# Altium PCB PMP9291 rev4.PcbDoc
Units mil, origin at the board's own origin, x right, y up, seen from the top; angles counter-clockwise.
Board outline 2000 x 2700 mil, 4 copper layers (Top Layer, MidLayer1, MidLayer2, Bottom Layer), stack 90 mil thick; 61 components, 21 nets, 125 pads, 4 vias.
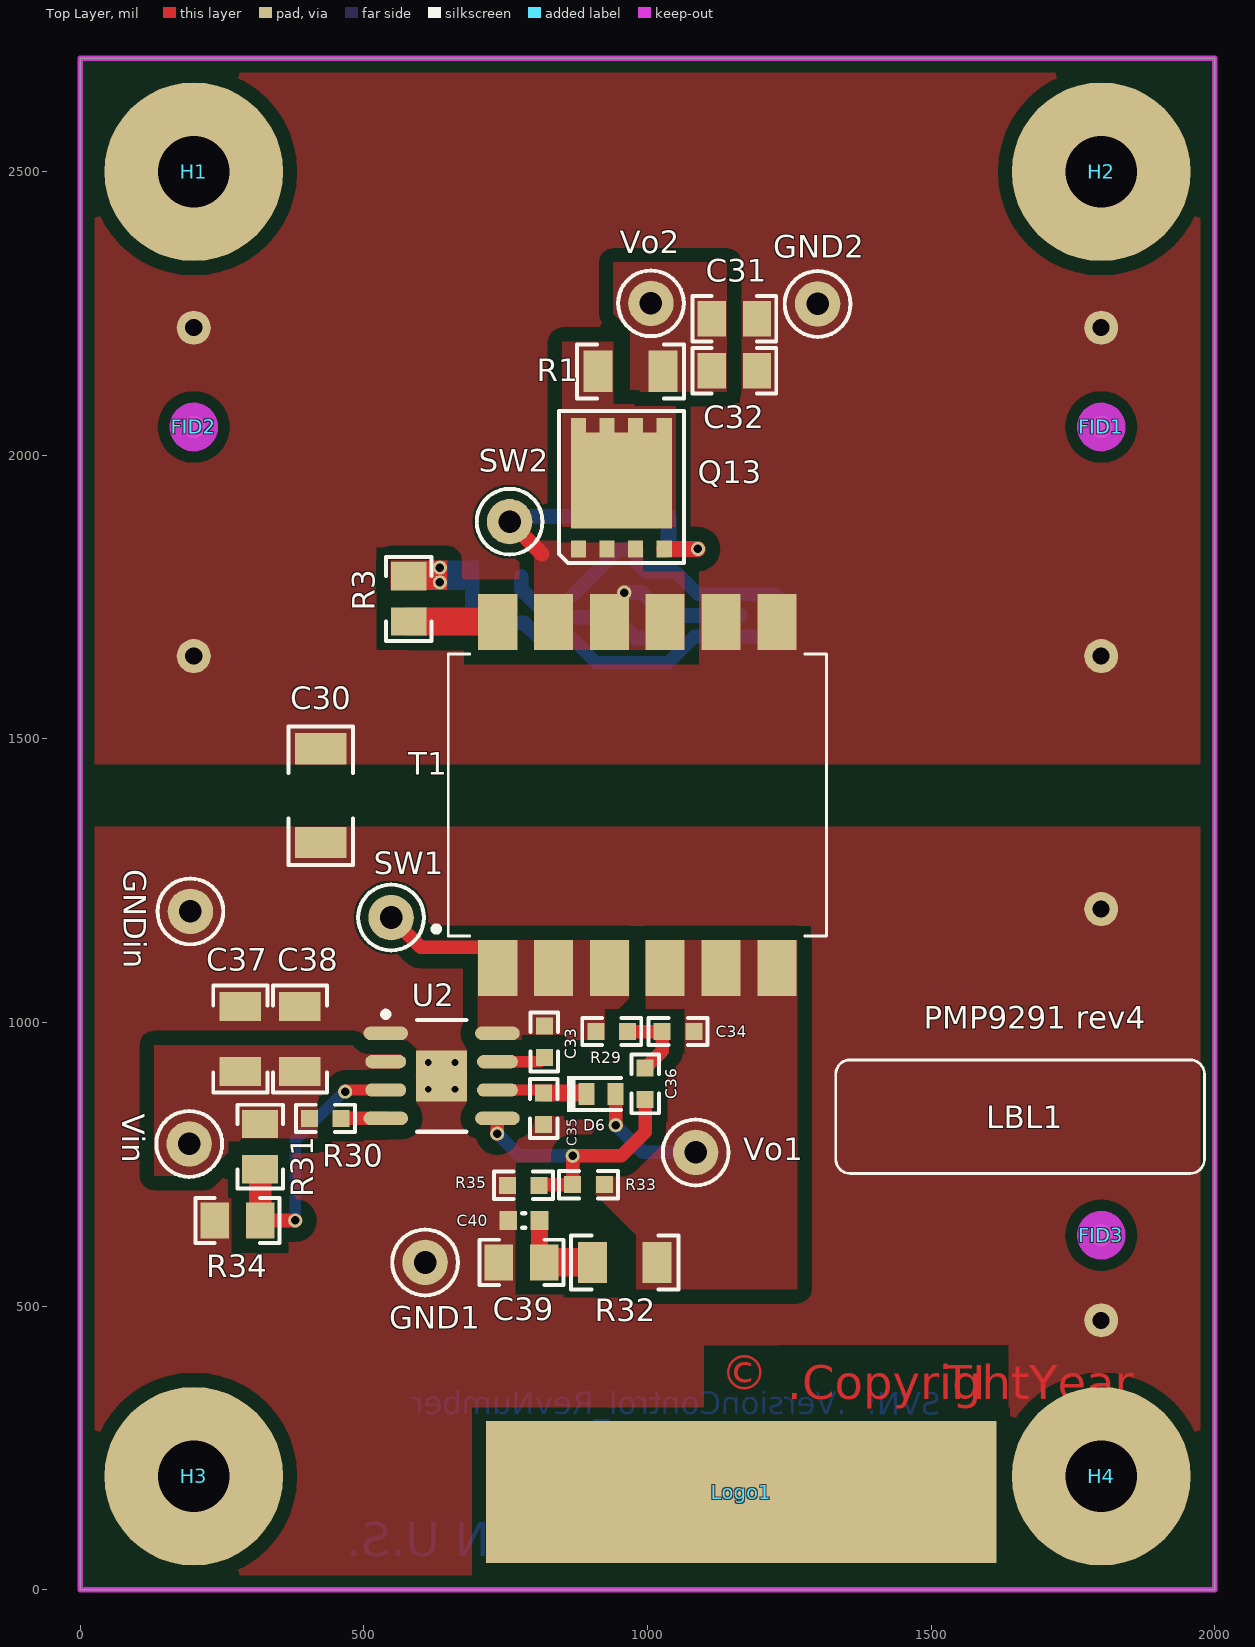
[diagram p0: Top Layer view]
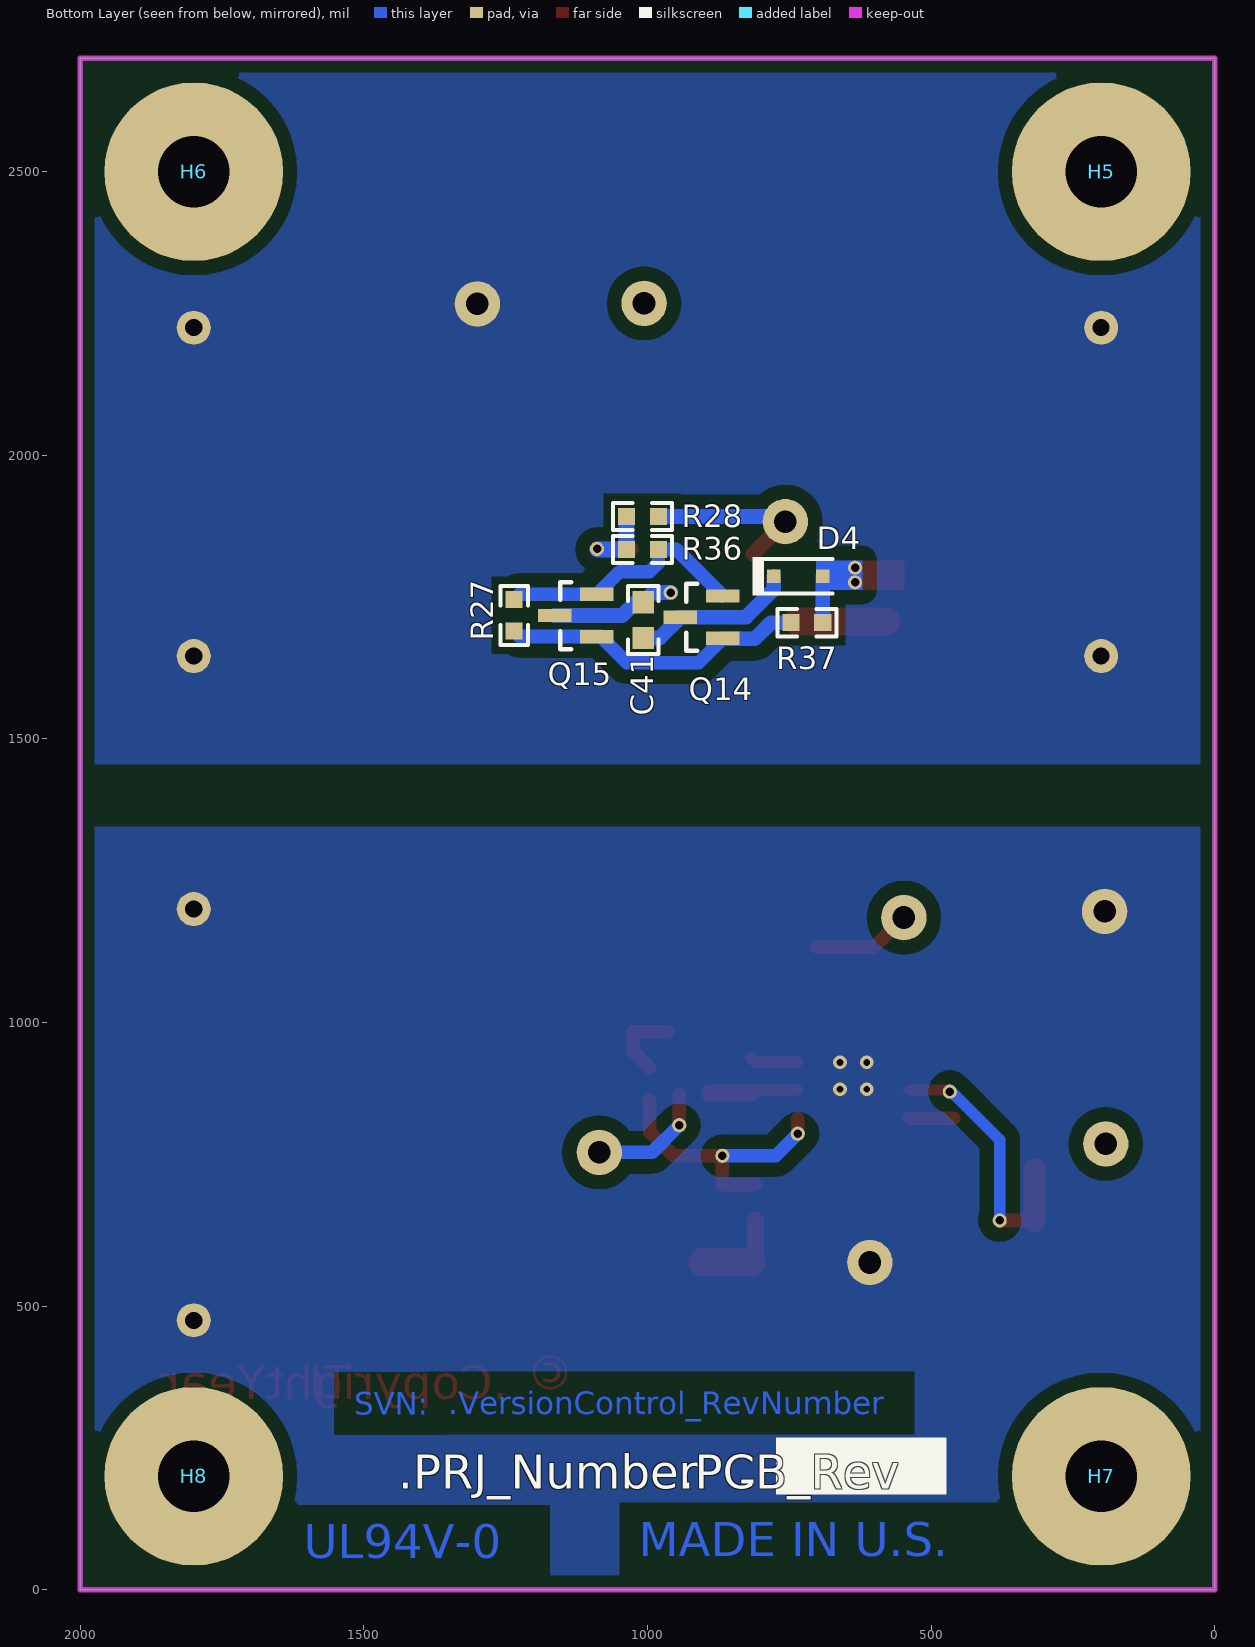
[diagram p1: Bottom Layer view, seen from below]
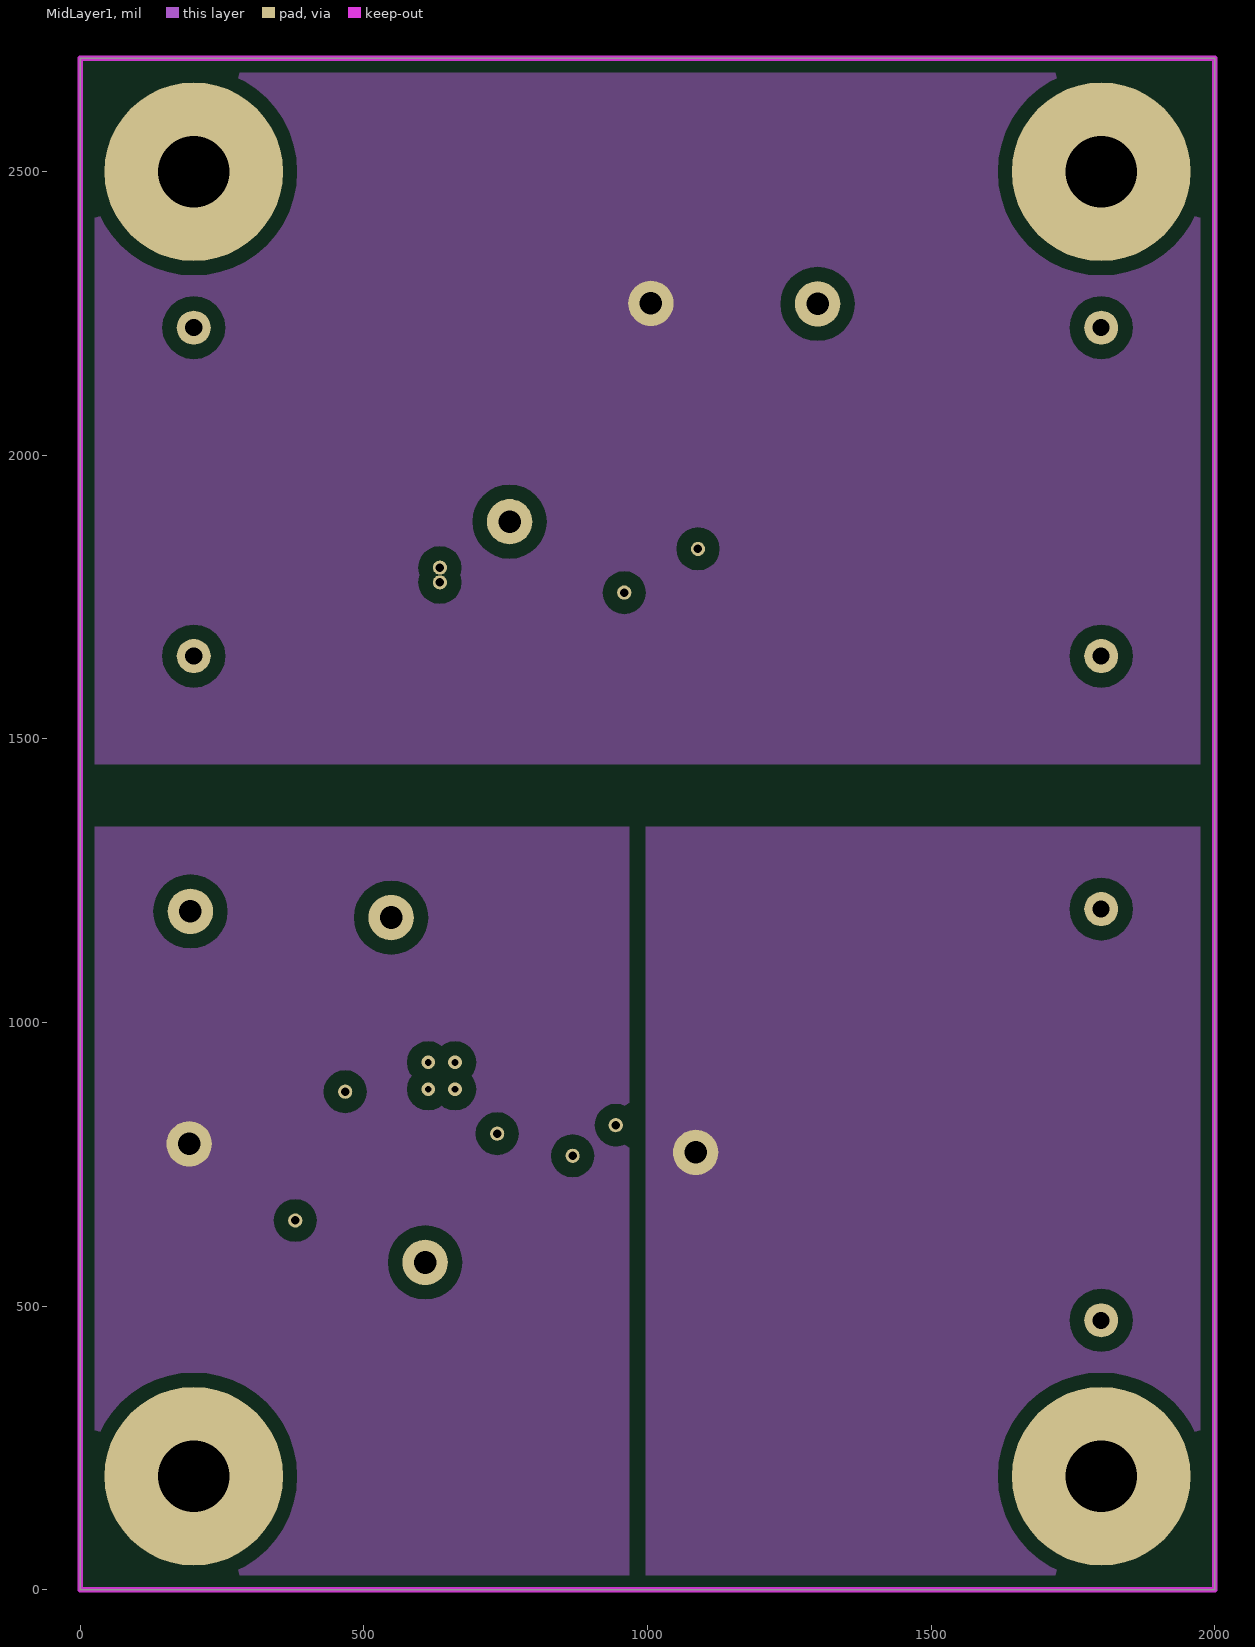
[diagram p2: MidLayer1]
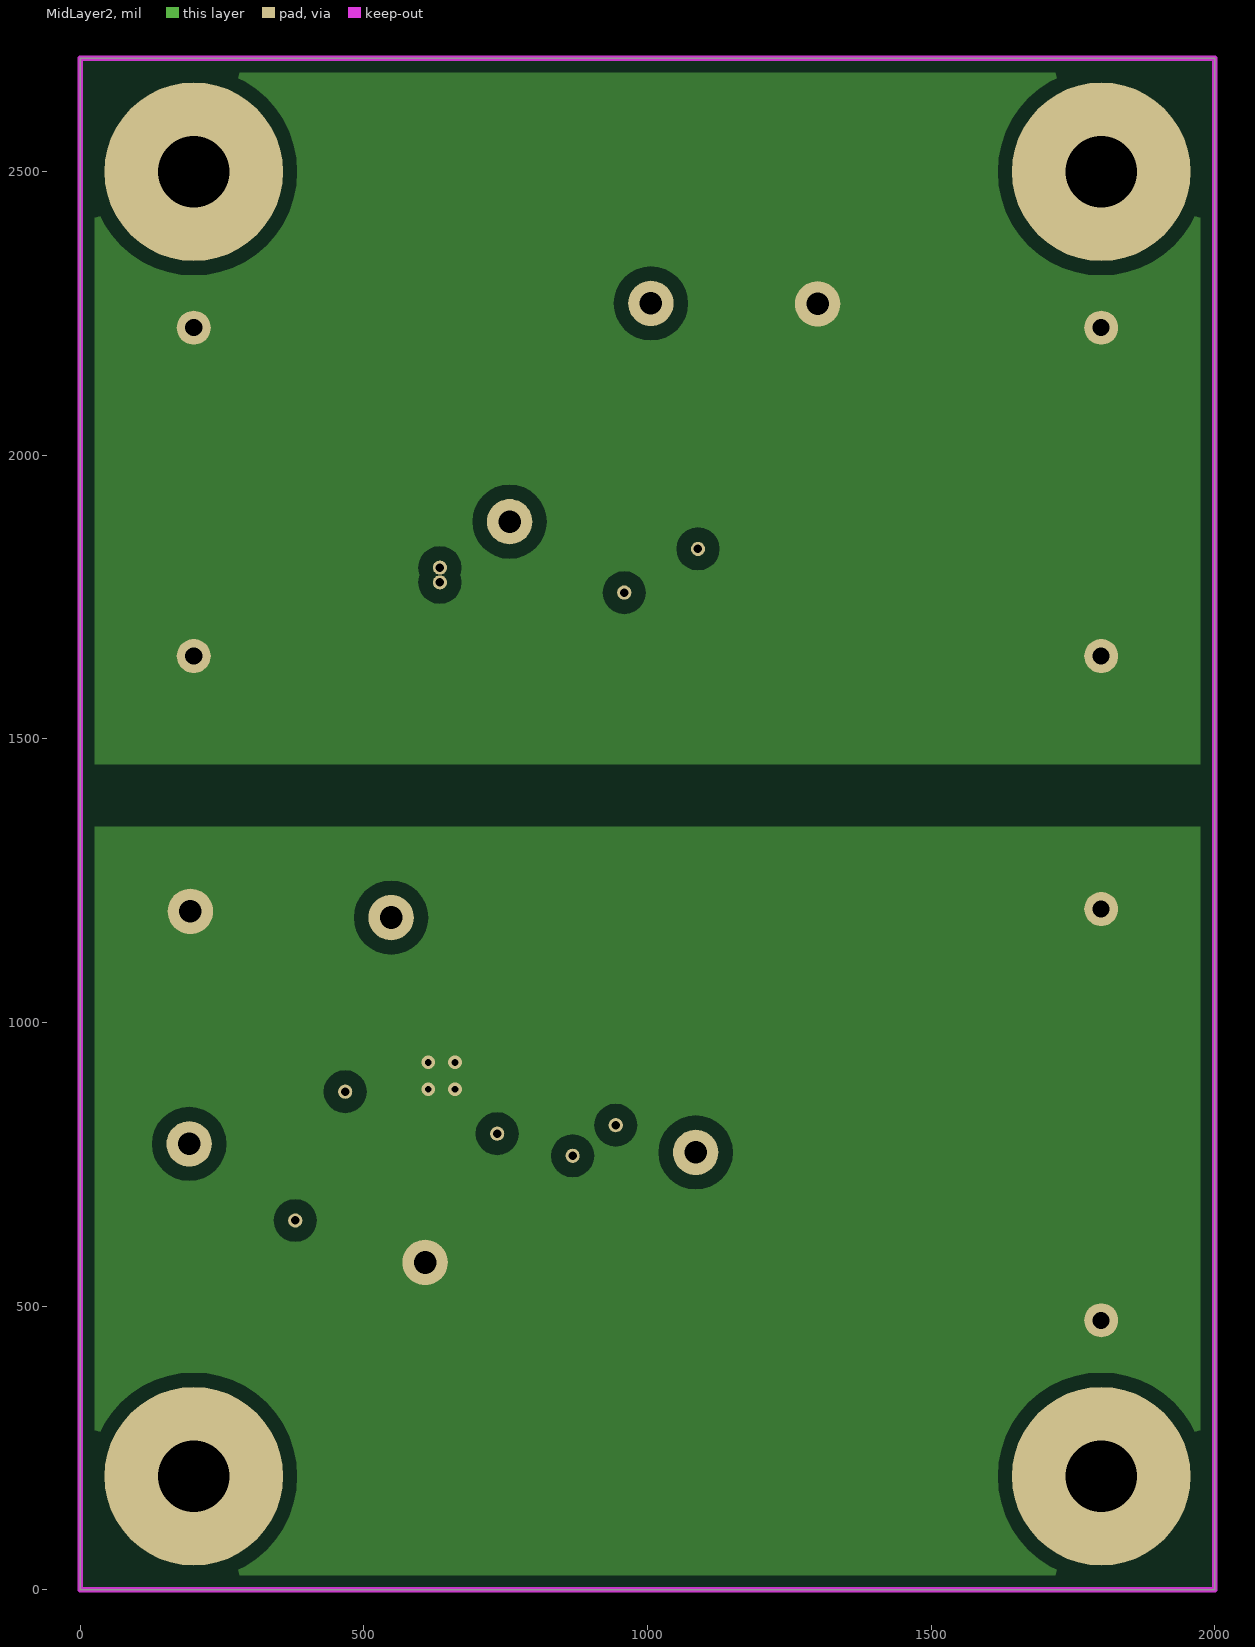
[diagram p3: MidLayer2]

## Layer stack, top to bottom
Top Solder: solder mask 0.4, Solder Resist, Dk 3.5
Top Layer: signal copper 1.4
Dielectric1: core 59.2, FR-4, Dk 4.8
MidLayer1: signal copper 1.4
Dielectric2: prepreg 12.6, FR-4, Dk 4.8
MidLayer2: signal copper 1.4
Dielectric3: core 12.6, FR-4, Dk 4.8
Bottom Layer: signal copper 1.4
Bottom Solder: solder mask 0.4, Solder Resist, Dk 3.5

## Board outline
0,0 2000,0 2000,2700 0,2700

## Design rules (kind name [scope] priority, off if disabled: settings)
AcuteAngle [All] p1: minimum=4.50000000000000E+0001 checktracksonly=FALSE
AssemblyTestPointUsage [All] p1: valid=2
Clearance Clearance_BoardEdge_MountingHoles [OnCopper and InComponentClass('Mounting Holes') vs IsKeepOut] p1: gap=30
Clearance Clearance_BoardEdge_Poly [OnCopper and InPoly vs IsKeepOut] p2: gap=20
Clearance Clearance_BoardEdge [OnCopper and Not InComponentClass('Logo') and not InComponentClass('FiducialMark') and not InRegion(1000,500,4000,800) and Not IsKeepout vs IsKeepOut] p3: gap=20
Clearance Clearance_Poly [InPolygon] p4: gap=25
Clearance [All] p5: gap=12
ComponentClearance ComponentClearance_Logo [InComponentClass('Logo')] p1: gap=20 collisioncheckmode=3 verticalgap=10 showdistances=FALSE
ComponentClearance ComponentClearance_ScrewToNut [(HasFootprint('NY PMS 440 0025 PH')) vs (HasFootprint('Keystone_1902C'))] p2: gap=5 collisioncheckmode=3 verticalgap=10 showdistances=FALSE
ComponentClearance ComponentClearance_MountingHoles [InComponentClass('Mounting Holes')] p3: gap=250 collisioncheckmode=3 verticalgap=100000 showdistances=FALSE
ComponentClearance ComponentClearance_SmallPassives [HasFootprint('0201*') or HasFootprint('0402*') or HasFootprint('0508') or HasFootprint('0603*') or HasFootprint('0612') or HasFootprint('0805*') or HasFootprint('0815*') or HasFootprint('0830*') or HasFootprint('1206*') or HasFootprint('1210*') or HasFootprint('1808*') or HasFootprint('1812*') or HasFootprint('1825*') or HasFootprint('2010*') or HasFootprint('2220*') or HasFootprint('2225*') or HasFootprint('2512*') or HasFootprint('2728*') or HasFootprint('3518*') vs HasFootprint('0201*') or HasFootprint('0402*') or HasFootprint('0508') or HasFootprint('0603*') or HasFootprint('0612') or HasFootprint('0805*') or HasFootprint('0815*') or HasFootprint('0830*') or HasFootprint('1206*') or HasFootprint('1210*') or HasFootprint('1808*') or HasFootprint('1812*') or HasFootprint('1825*') or HasFootprint('2010*') or HasFootprint('2220*') or HasFootprint('2225*') or HasFootprint('2512*') or HasFootprint('2728*') or HasFootprint('3518*')] p4: gap=20 collisioncheckmode=3 verticalgap=10 showdistances=FALSE
ComponentClearance ComponentClearance_THtoSMT [IsThruComponent vs IsSMTComponent] p5: gap=10 collisioncheckmode=3 verticalgap=30 showdistances=FALSE
ComponentClearance ComponentClearance_THtoTH [IsThruComponent vs IsThruComponent] p6: gap=10 collisioncheckmode=3 verticalgap=30 showdistances=FALSE
ComponentClearance [All] p7: gap=10 collisioncheckmode=3 verticalgap=10 showdistances=FALSE
DiffPairsRouting [All] p1: maxlimit=100 minlimit=10 mostfreqgap=10 toplayer_minwidth=15 toplayer_maxwidth=15 toplayer_prefwidth=15 midlayer1_minwidth=15 midlayer1_maxwidth=15 midlayer1_prefwidth=15 midlayer2_minwidth=15 midlayer2_maxwidth=15 midlayer2_prefwidth=15 bottomlayer_minwidth=15 bottomlayer_maxwidth=15 bottomlayer_prefwidth=15 maxuncoupledlength=1000
FabricationTestPointUsage TestPointUsage [All] p1: valid=2 allowmultiple=FALSE
FabricationTestpoint Testpoint [All] p1: side=3 testpointundercomponent=TRUE minsize=40 maxsize=100 preferedsize=60 minholesize=0 maxholesize=40 preferedholesize=32 testpointgrid=1 allowsidetop=TRUE allowsidebottom=TRUE usegrid=TRUE gridtolerance=0.01
FanoutControl Fanout_LCC [IsLCC] p1: bgadir=Out bgaviamode=Centered fanoutstyle=Auto fanoutdirection=Alternating viagrid=1 // Fanout_LCC (Default Rule)
FanoutControl Fanout_BGA [IsBGA] p2: bgadir=Out bgaviamode=Centered fanoutstyle=Auto fanoutdirection=Alternating viagrid=1 // Fanout_BGA (Default Rule)
FanoutControl Fanout_Default [All] p4: bgadir=Out bgaviamode=Centered fanoutstyle=Auto fanoutdirection=Alternating viagrid=1 // Fanout_Default (Default Rule)
FanoutControl Fanout_Small [(CompPinCount < 5)] p5: bgadir=Out bgaviamode=Centered fanoutstyle=Auto fanoutdirection=OutThenIn viagrid=1 // Fanout_Small (Default Rule)
HoleSize [All] p1: absolutevalues=TRUE maxlimit=251 minlimit=10 maxpercent=80.000 minpercent=20.000
MinimumAnnularRing MinimumAnnularRing_ThermalPadVias [IsVia and InAnyComponent] p1: minimumring=5.91
MinimumAnnularRing [All] p2: minimumring=5
MinimumSolderMaskSliver MinimumSolderMaskSliver_Logo [InComponentClass('Logo') vs InComponentClass('Logo')] p1: minsoldermaskwidth=0.7
MinimumSolderMaskSliver [All] p2: minsoldermaskwidth=3.94
PlaneClearance [All] p1: clearance=12
PlaneConnect [All] p1: planeconnectstyle=Direct reliefexpansion=10 reliefentries=4 reliefconductorwidth=10 reliefairgap=10
PolygonConnect [All] p1: connectstyle=Direct reliefconductorwidth=10 reliefentries=4 polygonreliefangle="90 Angle" airgapwidth=10
RoutingVias ThermalPadVias [IsVia and InAnyComponent] p1: holewidth=7.87 width=19.68 viastyle="Through Hole" minholewidth=7.87 minwidth=19.68 maxholewidth=12.99 maxwidth=23.62
RoutingVias [All] p2: holewidth=16 width=34 viastyle="Through Hole" minholewidth=7.87 minwidth=26 maxholewidth=40 maxwidth=65
SMDToCorner [All] p1: distance=30000
SilkToSilkClearance [All] p1: silktosilkclearance=5
SilkToSolderMaskClearance SilkscreenOverComponentPads [IsPad] p1: minsilkscreentomaskgap=5 clearancetoexposedcopper=TRUE
SolderMaskExpansion [All] p1: expansion=6
UnpouredPolygon [All] p1: allowunpoured=FALSE
Width [All] p1: maxlimit=100 minlimit=6 preferedwidth=10 checkconnectedcopper=TRUE
14 further rules are at their usual default settings.

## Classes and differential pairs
component class Label: LBL1
component class AssemblyNote: ZZ1 ZZ2 ZZ3 ZZ4
component class FiducialMark: FID1 FID2 FID3
component class "PMP9291 rev4 Hardware_ANSI-B": FID1 FID2 FID3 H1 H2 H3 H4 H5 H6 H7 H8 H9 H10 H11 H12 LBL1 Logo1 ZZ1 ZZ2 ZZ3 ZZ4
component class Logo: Logo1
component class "Mounting Holes": H1 H2 H3 H4
component class "PMP9291 Rev4 Schematic": C30 C31 C32 C33 C34 C35 C36 C37 C38 C39 C40 C41 D4 D6 GND1 GND2 GNDin Q13 Q14 Q15 R1 R3 R27 R28 R29 R30 R31 R32 R33 R34 R35 R36 R37 SW1 SW2 T1 U2 Vin Vo1 Vo2

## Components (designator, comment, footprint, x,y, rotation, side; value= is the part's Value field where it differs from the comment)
C30 "VJ1210Y102KXGAT5Z" 1808 424,1400 r90 top
C31 "2.2uF" 0805_HV 1153,2241 r0 top
C32 "2.2uF" 0805_HV 1153,2149 r0 top
C33 "GRM188R71C103KA01D" 0603_HV 818,966 r270 top
C34 "06035C104KAT2A" 0603_HV 1054,984 r180 top
C35 "C0603C105K4PACTU" 0603_HV 817,848 r270 top
C36 "06031C103JAT2A" 0603_HV 996,892 r270 top
C37 "GRM31CR61H225KA88L" 1206 282,971 r90 top
C38 "GRM31CR61H225KA88L" 1206 387,971 r90 top
C39 "C2012X7R1C225K" 0805_HV 778,577 r180 top
C40 "DNP" 0603L 782,651 r180 top
C41 "06035C104KAT2A" 0603 1007.44,1709.56 r90 bottom
D4 "BAS316,115" sod-323 734,1787 r180 bottom
D6 "CD0603-B0240" Diode_0603 918,874 r0 top
FID1 "Fiducial" Fiducial10-20 1800,2050 r0 top
FID2 "Fiducial" Fiducial10-20 200,2050 r0 top
FID3 "Fiducial" Fiducial10-20 1800,625 r0 top
GND1 "5001" Keystone5001 608,577 r0 top
GND2 "5001" Keystone5001 1300,2267 r90 top
GNDin "5001" Keystone5001 194,1196 r0 top
H1 "NY PMS 440 0025 PH" "NY PMS 440 0025 PH" 200,2500 r0 top locked
H2 "NY PMS 440 0025 PH" "NY PMS 440 0025 PH" 1800,2500 r0 top locked
H3 "NY PMS 440 0025 PH" "NY PMS 440 0025 PH" 200,200 r0 top locked
H4 "NY PMS 440 0025 PH" "NY PMS 440 0025 PH" 1800,200 r0 top locked
H5 "1902C" Keystone_1902C 200,2500 r180 bottom locked
H6 "1902C" Keystone_1902C 1800,2500 r180 bottom locked
H7 "1902C" Keystone_1902C 200,200 r180 bottom locked
H8 "1902C" Keystone_1902C 1800,200 r180 bottom locked
H9 "SJ-5303 (CLEAR)" Bumpon_SJ5003Transparent 7730,2620 r180 bottom
H10 "SJ-5303 (CLEAR)" Bumpon_SJ5003Transparent 8510,2720 r180 bottom
H11 "SJ-5303 (CLEAR)" Bumpon_SJ5003Transparent 7540,1640 r180 bottom
H12 "SJ-5303 (CLEAR)" Bumpon_SJ5003Transparent 8440,1640 r180 bottom
LBL1 "Size: 0.65\" x 0.20 \"" Label_650x200 1657,834 r0 top
Logo1 "Texas Instruments" TI_Stacked_SolderMask_Small 1165,172 r0 top
Q13 "CSD18537NQ5A" TRANS_NexFET_Q5A 954,1944 r90 top
Q14 "MMBT3904-7-F" SOT-23 904.44,1714.56 r0 bottom
Q15 "MMBT3906" SOT-23 1126.44,1717.56 r0 bottom
R1 "CRCW12060000Z0EA" 1206 970,2148 r0 top
R3 "CRCW08050000Z0EA" 0805_HV 579,1747 r90 top
R27 "CRCW060310R0JNEA" 0603_HV 1235,1718 r90 bottom
R28 "CRCW06032K00FKEA" 0603_HV 1009,1892 r180 bottom
R29 "CRCW060310K0FKEA" 0603_HV 937,984 r0 top
R30 "CRCW0603137KFKEA" 0603_HV 432,831 r0 top
R31 "CRCW0805127KFKEA" 0805_HV 317,781 r90 top
R32 "CRCW12060000Z0EA" 1206 960,577 r0 top
R33 "CRCW06036K04FKEA" 0603_HV 896,714 r0 top
R34 "DNP" 0805_HV 277,651 r0 top
R35 "CRCW06032K00FKEA" 0603_HV 781,713 r0 top
R36 "CRCW060310R0JNEA" 0603_HV 1009,1834 r180 bottom
R37 "CRCW06031K00FKEA" 0603_HV 719,1705 r0 bottom
SW1 "5000" Keystone5000 548,1185 r0 top
SW2 "5000" Keystone5000 757,1883 r0 top
T1 "VP2xxxx_VPH2xxxx" VP2_VPH2 982,1401 r90 top
U2 "LM5017MR" MRA08A_N 637,906 r0 top
Vin "5000" Keystone5000 192,786 r0 top
Vo1 "5000" Keystone5000 1085,771 r0 top
Vo2 "5000" Keystone5000 1006,2268 r270 top
ZZ1 "This Assembly Note is for PCB labels only" AssemblyNoteLabel 185,3938 r0 top
ZZ2 "These assemblies are ESD sensitive, ESD precautions shall be observed." AssemblyNote 185,3829.11 r0 top
ZZ3 "These assemblies must be clean and free from flux and all contaminants. Use of no clean flux is not acceptable." AssemblyNote 185,3740.56 r0 top
ZZ4 "These assemblies must comply with workmanship standards IPC-A-610 Class 2, unless otherwise specified." AssemblyNote 185,3652 r0 top

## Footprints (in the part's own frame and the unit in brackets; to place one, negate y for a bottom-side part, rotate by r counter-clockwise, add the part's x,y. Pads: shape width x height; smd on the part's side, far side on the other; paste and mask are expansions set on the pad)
0603 [mm] "0603 from SM-752 data"
  rect 1x0.95 smd: 1(-0.8,0) 2(0.8,0)
  silkscreen extent -1.52,-0.69 1.52,0.69, body extent -0.87,-0.47 0.87,0.47, height 0.85
0603_HV [mil] "Ernesto recommended land pattern.  26 mil between pads."
  rect 30x30 smd: 1(-28,0) 2(28,0)
  silkscreen extent -52,-24 52,24, body extent -34,-19 34,19, height 33
0603L [mm] "0603 from SM-752 data"
  rect 0.8x0.85 smd: 1(-0.7,0) 2(0.7,0)
  silkscreen extent -0.07,-0.33 0.07,0.33, body extent -0.87,-0.47 0.87,0.47, height 0.85
0805_HV [mil] "0805 with 30mil clearance between pads"
  rect 50x63 smd: 1(-40,0) 2(40,0)
  silkscreen extent -74,-40 74,40, body extent -43,-29 43,29, height 43
1206 [mm] "1206 from SM-752 data"
  rect 1.3x1.85 smd: 1(-1.45,0) 2(1.45,0)
  silkscreen extent -2.4,-1.21 2.4,1.21, body extent -1.7,-0.9 1.7,0.9, height 1.35
1808 [mm] "Chip Capacitor, Body 4.6x2.0mm, IPC Medium Density"
  rect 1.4x2.3 smd: 1(-2.1,0) 2(2.1,0)
  silkscreen extent -3.1,-1.45 3.1,1.45, body extent -2.47,-1.2 2.47,1.2, height 2.03
AssemblyNote [mil] "Assembly Note"
AssemblyNoteLabel [mil] "Assembly Note for PCB Labels"
Bumpon_SJ5003Transparent [mil] "3M Hemispherical Bumpon transparent"
  round 1 on Mech4: 0(0,0)
  body extent -217,-218 219,218, height 197
Diode_0603 [mm] "Based on Bourns recommended land pattern Rev 10/09"
  rect 0.7x1 smd: 1(-0.65,0) 2(0.65,0)
  silkscreen extent -1.5,-0.8 0.9,0.8, body extent -0.9,-0.5 0.9,0.5, height 0.85
Fiducial10-20 [mm]
  round 1 smd paste-0.5 mask+0.5: 1(0,0)
  Top Layer keep-out circle w1.178: c0,0 r0.5
Keystone5000 [mil] "For Keystone 500x miniature loop terminals"
  round 80 hole 40: 1(0,0)
  silkscreen extent -58,-58 58,58, body extent -49,-49 49,49, height 182
Keystone5001 [mil] "For Keystone 500x miniature loop terminals"
  round 80 hole 40: 1(0,0)
  silkscreen extent -58,-58 58,58, body extent -49,-49 49,49, height 182
Keystone_1902C [mil] "Hex Standoff, 4-40 threaded, nylon"
  body extent -145,-126 146,126, height 501
Label_650x200 [mil] "Thermal Transfer Label"
  silkscreen extent -325,-100 325,100, body extent -326,-101 326,101, height 1
MRA08A_N [mm] "SOIC, 8-Leads, Body 4.9x3.9mm, Pitch 1.27mm, Exposed Pad, IPC Medium Density"
  oval 2x0.6 smd: 1(-2.5,1.905) 4(-2.5,-1.905) 5(2.5,-1.905) 8(2.5,1.905)
  oval 1.829x0.6 smd: 2(-2.5,0.635) 3(-2.5,-0.635) 6(2.5,-0.635) 7(2.5,0.635)
  rect 2.29x2.29 smd: 9(0,0)
  silkscreen extent -2.62,-2.5 1.1,2.88, body extent -2,-2.5 2,2.5, height 1.68
"NY PMS 440 0025 PH" [mm] "4-40 nylon screw and mounting hole"
  round 8 hole 3.2: 1(0,0)
  body extent -3.3,-3.3 3.3,3.3, height 2.69
sod-323 [mm] "NXP recommended land pattern"
  rect 0.6x0.6 smd paste-0.05: 1(-1.1,0) 2(1.1,0)
  silkscreen extent -2.06,-0.86 1.53,0.86, body extent -1.3,-0.67 1.3,0.68, height 1.1
SOT-23 [mm] "SOT23, 3-Leads, Body 2.9x1.3mm, Pitch 0.95mm, Lead Span 2.5mm, IPC Medium Density"
  rect 1.5x0.6 smd: 1(-0.95,0.95) 2(-0.95,-0.95) 3(0.95,0)
  silkscreen extent 0.2,-1.5 0.7,1.5, body extent -1.16,-1.45 1.21,1.45, height 1
TI_Stacked_SolderMask_Small [mil]
  rect 900x250 smd paste-125 mask-125: 0(0,0)
TRANS_NexFET_Q5A [mm] "TI recommended land pattern (nominal) M0139-01"
  rect 0.75x0.675 smd paste-0.1 mask+0.051: 1(-2.776,1.917) 2(-2.776,0.639) 3(-2.776,-0.639) 4(-2.776,-1.917)
  rect 0.655x0.675 smd paste-0.1 mask+0.051: 5(2.776,-1.917) 6(2.776,-0.639) 7(2.776,0.639) 8(2.776,1.917)
  rect 4.295x4.51 smd paste-2.2 mask+0.051: 9(0.301,0)
  silkscreen extent -3.4,-2.8 3.4,2.8, body extent -3.05,-2.5 3.05,2.5, height 1.11
VP2_VPH2 [mm]
  rect 2.5x1.75 smd: 1(-7.75,6.25) 2(-7.75,3.75) 3(-7.75,1.25) 4(-7.75,-1.25) 5(-7.75,-3.75) 6(-7.75,-6.25) 7(7.75,-6.25) 8(7.75,-3.75) 9(7.75,-1.25) 10(7.75,1.25) 11(7.75,3.75) 12(7.75,6.25)
  silkscreen extent -6.32,-8.47 6.32,9.13

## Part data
C30: "Ceramic, X7R, 1000V, 10%"
C31 C32 C40: library part GRM21BR71E225KA73L, "CAP, CERM, 2.2uF, 25V, +/-10%, X7R, 0805"
C33: "CAP, CERM, 0.01uF, 16V, +/-10%, X7R, 0603"
C34 C41: "CAP, CERM, 0.1uF, 50V, +/-10%, X7R, 0603"
C35: "CAP, CERM, 1uF, 16V, +/-10%, X5R, 0603"
C36: "CAP, CERM, 0.01uF, 100V, +/-5%, X7R, 0603"
C37 C38: "CAP, CERM, 2.2uF, 50V, +/-10%, X5R, 1206"
C39: "CAP, CERM, 2.2uF, 16V, +/-10%, X7R, 0805"
D4: "Diode, Ultrafast, 100V, 0.25A, SOD-323"
D6: "Diode, Schottky, 45V, 0.2A, 0603 Diode"
FID1 FID2 FID3: "Fiducial mark.  There is nothing to buy or mount."
GND1 GND2 GNDin: "Test Point, TH, Miniature, Black"
H1 H2 H3 H4: "Machine Screw, Round, #4-40 x 1/4, Nylon, Philips panhead"
H5 H6 H7 H8: "Standoff, Hex, 0.5\"L #4-40 Nylon"
H9 H10 H11 H12: "Bumpon, Hemisphere, 0.44 X 0.20, Clear"
LBL1: library part THT-14-423-10, "Thermal Transfer Printable Labels, 0.650\" W x 0.200\" H - 10,000 per roll"
Logo1: library part TI_Logo, "Texas Instrument Corporate Signature"
Q13: "MOSFET, N-CH, 60V, 50A, SON 5x6mm"
Q14: library part "MMBT3904-7-F, Diodes Inc.", "Transistor, NPN, 40V, 0.2A, SOT-23"
Q15: library part "MMBT3906, Fairchild Semiconductor", "Transistor, PNP, 40V, 0.2A, SOT-23"
R1 R32: "RES, 0 ohm, 5%, 0.25W, 1206"
R3: "RES, 0 ohm, 5%, 0.125W, 0805"
R27 R36: "RES, 10 ohm, 5%, 0.1W, 0603"
R28 R35: "RES, 2.00k ohm, 1%, 0.1W, 0603"
R29: "RES, 10.0k ohm, 1%, 0.1W, 0603"
R30: "RES, 137k ohm, 1%, 0.1W, 0603"
R31: "RES, 127k ohm, 1%, 0.125W, 0805"
R33: "RES, 6.04k ohm, 1%, 0.1W, 0603"
R34: library part CRCW08058K25FKEA, "RES, 8.25k ohm, 1%, 0.125W, 0805"
R37: "RES, 1.00k ohm, 1%, 0.1W, 0603"
SW1 SW2 Vin Vo1 Vo2: "Test Point, TH, Miniature, Red"
T1: library part VP2_VPH2, "1:1:1:1:1:1 Turns Ratio Versatile Transformers"
U2: library part LM5017
ZZ1: library part AssemblyNoteLabel
ZZ2 ZZ3 ZZ4: library part AssemblyNote

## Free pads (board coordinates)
  round 60 hole 30: 0(200,1646) 1(1800,1646) 2(1800,2225) 3(200,2225) 4(1800,1200) 5(1800,475)
  round 25 hole 15: 0(379,651) 0(467,878) 0(634,1776) 0(634,1802) 0(735,804) 0(868,765) 0(944,819) 0(959,1758) 0(1089,1835)

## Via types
v1: diameter 24, hole 12, Top Layer to Bottom Layer, tented top, 4 vias

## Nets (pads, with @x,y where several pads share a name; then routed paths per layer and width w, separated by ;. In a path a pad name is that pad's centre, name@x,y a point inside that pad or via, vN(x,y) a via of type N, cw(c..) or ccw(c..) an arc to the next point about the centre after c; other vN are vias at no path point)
+VFLOATING: C41.1 D4.1 Q14.3 | length 288.9
  Bottom Layer w26: D4.1 777.31,1763.69 826.44,1714.56 Q14.3 978.34,1678.06 C41.1
BST: C33.2 U2.7 | length 85.5
  Top Layer w20: U2.7 811,931 C33.2
"DRVR IN": Q14.1 Q15.1 R27.1 R37.2 | length 539.5
  Bottom Layer w24: Q14.1@867.34,1676.86 909.82,1634.38 1036.08,1634.38 Q15.1@1081.86,1680.16 ; Q15.1@1082.26,1680.56 1225.56,1680.56 R27.1
  Bottom Layer w26: R37.2 782.26,1705 810.7,1676.56 Q14.1@867.04,1676.56
"DRVR OUT": Q14.2 Q15.2 R27.2 R36.2 | length 452.5
  Bottom Layer w24: Q14.2 949.08,1834 R36.2 981,1810 996,1795 1049,1795 Q15.2 1226.04,1754.96 R27.2
EN: pad.0@379,651 pad.0@467,878 R31.1 R34.2 U2.3 | length 490
  Top Layer w20: pad.0@467,881 U2.3
  Top Layer w24: R34.2 pad.0@379,651
  Top Layer w40: R34.2 R31.1
  Bottom Layer w20: pad.0@379,651 379,793 pad.0@467,881
FB: C36.2 pad.0@735,804 pad.0@868,765 R33.1 R35.2 U2.5 | length 487.1
  Top Layer w24: pad.0@735,804 U2.5@735,830.57 ; R35.2@810,714 R33.1 868,765 954,765 996,807 C36.2
  Bottom Layer w24: pad.0@735,804 774,765 pad.0@868,765
GATE: pad.0@1089,1835 Q13.4 R28.1 R36.1 | length 168.2
  Top Layer w28: Q13.4 pad.0@1088.7,1834.7
  Bottom Layer w28: R28.1 R36.1 pad.0@1088,1834
GND: C30.1 C35.2 C37.2 C38.2 C39.2 C40.2 GND1.1 GNDin.1 pad.4 pad.5 R34.1 R35.1 U2.1 U2.9
  other v1: 613.38,882.38 660.62,882.38 613.38,929.62 660.62,929.62
IGND: C30.2 C31.2 C32.2 GND2.1 pad.0@200,1646 pad.1 pad.2 pad.3 T1.7 T1.8
NetQ13_5: Q13.5 Q13.6 Q13.7 Q13.8 Q13.9 R1.1
NetR3_1: R3.1 T1.12 | length 156.1
  Top Layer w50: R3.1 T1.12@735.06,1707
NetR30_2: R30.2 U2.4 | length 78.6
  Top Layer w24: R30.2 U2.4
RIPPLERC: C34.2 C36.1 R29.2 | length 137.4
  Top Layer w24: R29.2 C34.2 1026,950 C36.1
SW1: C33.1 R29.1 SW1.1 T1.1 T1.2 T1.3 U2.8 | length 174.5
  Top Layer w24: SW1.1 600,1133 701,1133
SW2: C41.2 pad.0@959,1758 Q13.1 Q13.2 Q13.3 Q15.3 R28.2 SW2.1 T1.9 T1.10 T1.11 | length 517.2
  Top Layer w26: SW2.1 814,1826
  Bottom Layer w26: SW2.1@766,1892 R28.2 ; pad.0@959,1758 990.5,1758 C41.2 1020.94,1741.06 1044.44,1717.56 Q15.3
VCC: C35.1 D6.1 U2.6 | length 148
  Top Layer w20: U2.6 C35.1@810,881
  Top Layer w30: C35.1 D6.1@890.41,876
"VFLOAT PRERECT": D4.2 pad.0@634,1776 pad.0@634,1802 R3.2 R37.1 | length 81.7
  Bottom Layer w25: R37.1 D4.2@691,1786.69
VIN: C37.1 C38.1 R30.1 R31.2 U2.2 Vin.1
VOUT1: C34.1 D6.2 pad.0@944,819 R32.2 R33.2 T1.4 T1.5 T1.6 Vo1.1 | length 215.5
  Top Layer w24: pad.0@944,819 D6.2@944,873.59
  Bottom Layer w24: pad.0@944,819 992,771 Vo1.1
VOUT1CAP: C39.1 C40.1 R32.1 | length 150.5
  Top Layer w30: C39.1@809.56,585.44 C40.1
  Top Layer w50: C39.1 R32.1
VOUT2: C31.1 C32.1 R1.2 Vo2.1
pads on no net: FID1.1 FID2.1 FID3.1 H1.1 H2.1 H3.1 H4.1 H9.0 H10.0 H11.0 H12.0 Logo1.0

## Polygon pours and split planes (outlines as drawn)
SW1 on Top Layer "Top Overlay-SW1" (solid, remove dead copper, pour order 21): 701,1145 712,1145 967,1145 968,1145 968,1142 968,1112 968,1047 968,1043 924,999 924,970 905,970 770,970 704,970 701,973 701,995 701,1145
VIN on Top Layer "Top Layer-Vin" (solid, remove dead copper, pour order 17): 500,960 523,960 566,960 566,900 542,900 454,900 419,865 419,847 419,831 419,796 398,796 285,796 219,730 179,730 130,730 130,754 130,881 130,950 130,960 160,960 500,960
VOUT1 on Top Layer "Top Layer-Vout1" (solid, pour order 18): 997,1145 1002,1145 1264,1145 1264,1122 1264,868 1264,617 1264,530 1242,530 980,530 980,564 980,625 909,696 909,708 909,730 997,818 997,1145
GND on Top Layer "Top Layer-GND" (solid, remove dead copper, pour order 19): 360,1345 363,1345 2000,1345 2000,1341 2000,0 0,0 0,1345
SW2 on Top Layer "Top Layer-SW2" (solid, remove dead copper, pour order 20): 992,1849 992,1845 992,1820 1012,1800 1065,1800 1065,1776 1065,1657 1042,1657 800,1657 800,1676 800,1849 815,1849 992,1849
NetQ13_5 on Top Layer "Top Layer-Vout2x" (solid, remove dead copper, pour order 22): 940,2200 940,2192 940,2090 962,2090 1050,2090 1050,2067 1050,1871 1023,1871 850,1871 850,1892 850,2092 850,2200 940,2200
VOUT2 on Top Layer "Top Layer-Vout2" (solid, remove dead copper, pour order 23): 1138,2112 1109,2112 1001,2112 970,2112 970,2121 970,2220 940,2250 940,2270 940,2340 968,2340 1140,2340 1140,2296 1140,2112 1139,2112
IGND on Top Layer "Top Layer-ISO GND" (solid, remove dead copper, pour order 24): 350,1455 357,1455 2000,1455 2000,2700 0,2700 0,1455 350,1455
IGND on Bottom Layer "Bottom Layer-ISO GND" (solid, remove dead copper, pour order 25): 2000,2700 0,2700 0,2697 0,1455 2000,1455 2000,2700
GND on Bottom Layer "Bottom Layer-GND" (solid, remove dead copper, pour order 26): 2000,1345 1995,1345 0,1345 0,1344 0,0 2000,0 2000,1345
VOUT2 on MidLayer1 "MidLayer1-Vout2" (solid, remove dead copper, pour order 27): 0,1455 2000,1455 2000,2700 0,2700 0,1455
VOUT1 on MidLayer1 "MidLayer1-Vout1" (solid, remove dead copper, pour order 29): 997,1345 1003,1345 2000,1345 2000,0 997,0 997,1345
VIN on MidLayer1 "MidLayer1-Vin" (solid, remove dead copper, pour order 30): 968,1345 968,0 0,0 0,1345 968,1345
IGND on MidLayer2 "MidLayer2-ISO GND" (solid, remove dead copper, pour order 28): 0,1455 2000,1455 2000,2700 0,2700 0,1455
GND on MidLayer2 "MidLayer2-GND" (solid, remove dead copper, pour order 31): 0,1345 2000,1345 2000,0 0,0 0,1345

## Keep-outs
Keep-Out Layer:
  the board outline again, w10
  text ".Layer_Name" at 577,-858.49 h60

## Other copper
Top Layer:
  rectangle net "VFLOAT PRERECT": 547,1763 647,1815
  text ".CopyrightYear" at 1246,336 h60
  text "TI" at 1522,336 h60
  text "©" at 1129,332.48 h105
  text ".Layer_Name" at 577,-858.49 h60
Bottom Layer:
  rectangle net "VFLOAT PRERECT": 621,1763 703,1815
  text ".VersionControl_RevNumber" at 1351,309 h40
  text "SVN:" at 1517,308.5 h40
  text "MADE IN U.S." at 1015,59 h60
  text "UL94V-0" at 1606,55 h60
  text ".Layer_Name" at 577,-858.49 h60

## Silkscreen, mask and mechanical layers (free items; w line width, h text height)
Top Overlay:
  text "PMP9291 rev4" at 1487,989 h40
  text ".Layer_Name" at 577,-858.49 h60
Bottom Overlay:
  rectangle: 473,168 773,268
  text ".PCB_Rev" at 943,178 h60
  text ".PRJ_Number" at 1439,178 h60
  text "-" at 838,167.5 h60
  text ".Layer_Name" at 577,-858.49 h60
Top Paste:
  text ".Layer_Name" at 577,-858.49 h60
Bottom Paste:
  text ".Layer_Name" at 577,-858.49 h60
Top Solder:
  text ".Layer_Name" at 577,-858.49 h60
  text ".Layer_Name" at 577,-858.49 h60
Bottom Solder:
  text ".Layer_Name" at 577,-858.49 h60
Drill Guide:
  text ".Layer_Name" at 577,-858.49 h60
M1 Board Outline:
  the board outline again, w10
  text ".Layer_Name" at 577,-858.49 h60
M2 Board Dimensions:
  rectangle: 124.5,-410.5 499.5,-285.5
  rectangle: -0.5,-285.5 124.5,-160.5
  lines w7: -0.5,-285.5 999.5,-285.5 ; 124.5,-410.5 124.5,-160.5 ; 249.5,-410.5 249.5,-160.5 ; 499.5,-410.5 499.5,-160.5 ; 749.5,-410.5 749.5,-160.5 ; -0.5,-410.5 -0.5,-160.5 999.5,-160.5 999.5,-410.5 -0.5,-410.5
  lines w10: -0.5,-475.5 -0.5,-455.5 ; 59.5,-485.5 -0.5,-465.5 ; 59.5,-445.5 -0.5,-465.5 ; 223.58,-465.5 -0.5,-465.5 ; 775.42,-465.5 999.5,-465.5 ; 939.5,-485.5 999.5,-465.5 ; 939.5,-445.5 999.5,-465.5 ; 999.5,-475.5 999.5,-455.5
  text "1000 (mil)" at 233.58,-501.49 h60
  text ".Layer_Name" at 577,-858.49 h60
M3 3D STEP Top:
  text ".Layer_Name" at 577,-858.49 h60
M4 3D STEP Bottom:
  text ".Layer_Name" at 577,-858.49 h60
M5 Assembly Top:
  lines w10: -292,-930.17 6308,-930.17 ; -292,-726.83 6310,-726.83 ; -292,-523.5 -292,-1133.5 3713,-1133.5 6310,-1133.5 6310,-523.5 -291.5,-523.5 -291.5,-1133.5 1284,-1133.5 ; 2173,-1133.5 2173,-523.5 ; 3440,-726.83 3440,-523.5 ; 4280,-726.83 4280,-523.5 ; 4902,-1140 4902,-937.17
  text "COMPONENTS MARKED 'DNP' SHOULD NOT BE POPULATED." at 1153.5,-318.5 h60
  text "ASSEMBLY VARIANT:" at 1153,-434 h60
  text ".VariantName" at 2189,-434 h60
  text "PCB VIEWED FROM TOP SIDE" at -228.5,-655.67 h60
  text "BOARD #:" at 2248,-655.67 h60
  text ".PRJ_Number" at 2793.5,-655.67 h60
  text "REV:" at 3638,-655.67 h60
  text ".PCB_Rev" at 3929.5,-655.67 h60
  text "SVN REV:" at 4476,-655.67 h60
  text ".VersionControl_RevNumber" at 4982,-655.67 h60
  text "IGNORE ->" at -228.5,-858.49 h60
  text "PLOT NAME =" at -228.5,-1064.34 h60
  text ".plot_File_Name" at 577,-1064.34 h60
  text "GENERATED    :" at 2250,-1064.34 h60
  text ".Print_Date" at 3119.5,-1064.34 h60
  text ".Print_Time" at 3848.5,-1064.34 h60
  text "TEXAS INSTRUMENTS" at 5113,-1064.34 h60
M6 Assembly Bottom:
  lines w10: -292.5,-727.33 6309.5,-727.33 ; -290.5,-930.67 6309.5,-930.67 ; 1115.5,-1140.5 1115.5,-937.67 ; 1737.5,-727.33 1737.5,-524 ; 2577.5,-727.33 2577.5,-524 ; 3844.5,-1134 3844.5,-524 ; 4733.5,-1134 6309,-1134 6309,-524 -292.5,-524 -292.5,-1134 2304.5,-1134 6309.5,-1134 6309.5,-524
  text "COMPONENTS MARKED 'DNP' SHOULD NOT BE POPULATED." at 6102,-318 h60
  text ".VariantName" at 5058,-434 h60
  text "ASSEMBLY VARIANT:" at 6097,-434 h60
  text ".VersionControl_RevNumber" at 1035.5,-656.17 h60
  text "SVN REV:" at 1541.5,-656.17 h60
  text ".PCB_Rev" at 2088,-656.17 h60
  text "REV:" at 2379.5,-656.17 h60
  text ".PRJ_Number" at 3224,-656.17 h60
  text "BOARD #:" at 3769.5,-656.17 h60
  text "PCB VIEWED FROM BOTTOM SIDE" at 6246,-656.17 h60
  text "IGNORE ->" at 2547.85,-858.49 h60
  text "TEXAS INSTRUMENTS" at 904.5,-1064.84 h60
  text ".Print_Time" at 2169,-1064.84 h60
  text ".Print_Date" at 2898,-1064.84 h60
  text "GENERATED    :" at 3767.5,-1064.84 h60
  text ".plot_File_Name" at 5440.5,-1064.84 h60
  text "PLOT NAME =" at 6246,-1064.84 h60
M9 Title Sheet:
  drawing of 57 lines, arcs and shapes, not listed
  text "1" at 739.84,8036.5 h70
  text "2" at 3235.5,8036.5 h70
  text "3" at 5724.84,8036.5 h70
  text "4" at 8231.51,8036.5 h70
  text "5" at 10730.5,8036.5 h70
  text "6" at 13235.5,8036.5 h70
  text "A" at -416.5,6893.5 h70
  text "A" at 14383.5,6893.5 h70
  text "B" at -416.5,4513.5 h70
  text "B" at 14383.5,4513.5 h70
  text "C" at -416.5,2138.5 h70
  text "C" at 14383.5,2138.5 h70
  text "PROJECT TITLE:" at 11343.5,277.5 h45
  text ".PRJ_Title" at 11393.5,144.17 h70
  text "DESIGNED FOR:" at 11343.5,-23.5 h45
  text ".PRJ_Customer" at 11393.5,-163.5 h70
  text "D" at -416.5,-231.5 h70
  text "D" at 14383.5,-231.5 h70
  text "FILE NAME:" at 11343.5,-323.5 h45
  text ".PCB_File_Name_No_Path" at 11393.5,-443.5 h70
  text "Texas Instruments (TI) and/or its licensors do not warrant the accuracy or completeness of this specification" at 6374,-605.34 h45
  text "ENGINEER:" at 11343.5,-613.5 h45
  text "LAYOUT BY:" at 12848.5,-613.5 h45
  text "or any information contained therein. TI and/or its licensors do not warrant that this design will meet" at 6329.01,-718 h45
  text ".PRJ_Engineer" at 11393.5,-768.49 h70
  text ".PCB_Layout" at 12899,-768.49 h70
  text "the specifications, will be suitable for your application or fit for any particular purpose, or will operate in" at 6329.01,-830.67 h45
  text ".Layer_Name" at 577,-858.49 h60
  text "ALTIUM DESIGNER VERSION:" at 12848.5,-923.5 h45
  text "an implementation. TI and/or its licensors do not warrant that the design is production worthy. You should" at 6329.01,-943.33 h45
  text "completely validate and test your design implementation to confirm the system functionality for your application." at 6374,-1056 h45
  text ".print_Scale" at 11393.5,-1056.83 h70
  text ".Application_BuildNumber" at 12899,-1056.83 h70
  text "1" at 739.84,-1263.5 h70
  text "2" at 3235.5,-1263.5 h70
  text "3" at 5724.84,-1263.5 h70
  text "4" at 8231.51,-1263.5 h70
  text "5" at 10730.5,-1263.5 h70
  text "6" at 13235.5,-1263.5 h70
M10 Fab Notes:
  drawing of 212 lines, arcs and shapes, not listed
  text "DESIGN INFORMATION" at 12381.02,6810 h60
  text "(REFER ALSO ARRAY/PANEL PROFILING INFORMATION)" at 12019.46,6648.29 h60
  text "BOARD SIZE" at 11333.46,6644 h60
  text "3450MIL" at 11795.78,6516.18 h60
  text "X" at 12301.46,6516.18 h60
  text "4950MIL" at 12532.78,6516.18 h60
  text "Number of Layers :" at 11736.46,6319 h60
  text "2" at 12831.27,6309 h60
  text "MIN. TRACK WIDTH:" at 11736.46,6180 h60
  text "8" at 12832.7,6180 h60
  text "MIL" at 12987.46,6180 h60
  text "MIN. CLEARANCE:" at 11736.46,6048 h60
  text "8" at 12832.7,6048 h60
  text "MIL" at 12987.46,6048 h60
  text "MIN. VIA PAD SIZE:" at 11736.46,5916 h60
  text "24" at 12802.71,5916 h60
  text "MIL" at 12987.46,5916 h60
  text "0.05mm (2MIL)" at 12431.46,5774.29 h60
  text "MINIMUM ANNULAR RING" at 11407.23,5770 h60
  text "EXTERNAL" at 13139.46,5770 h60
  text "PER" at 11607.23,5652 h60
  text "IPC-D-275 CLASS 2 LEVEL C" at 11827.23,5652 h60
  text "MIL, HOLES" at 13315.46,5539.71 h60
  text "+/-" at 12923,5539 h60
  text "+/-" at 13777,5539 h60
  text "REGISTRATION TOLERANCES:" at 11407.23,5534 h60
  text "METAL" at 12607,5534 h60
  text "5" at 13183.2,5534 h60
  text "3" at 14016.2,5534 h60
  text "MIL" at 14132.46,5534 h60
  text "MATERIAL:" at 11332.46,5324.54 h60
  text "FR-4 High Tg" at 12318.9,5184.21 h60
  text "FR-408" at 11753.46,5175.64 h60
  text "X" at 12165.46,5175.64 h60
  text "OTHER" at 13241.46,5175.64 h60
  text "62 MIL (1.6mm) +/-10%" at 12073.56,5012.92 h60
  text "THICKNESS:" at 11407.23,5008.64 h60
  text "X" at 11945.4,5008.64 h60
  text "OTHER" at 13358.46,5008.64 h60
  text "TOLERANCE:" at 11407.23,4850.64 h60
  text "X" at 12246.53,4850.64 h60
  text "ANSI IPC-6012 TYPE 3 CLASS 2" at 12433.48,4850.64 h60
  text "OTHER +/-" at 12433.46,4694.64 h60
  text "BOW & TWIST:" at 11407.23,4537.64 h60
  text "X" at 12246.53,4537.64 h60
  text "ANSI IPC-6012 TYPE 3 CLASS 2" at 12433.48,4537.64 h60
  text "OTHER +/-" at 12433.46,4379.13 h60
  text "COPPER THICKNESS (FINISHED):" at 11332.46,4243.64 h60
  text "1.4MIL (1oz)" at 12212.46,4090.92 h60
  text "2MIL (1.4oz)" at 12979.46,4090.92 h60
  text "2.8MIL (2oz)" at 13706.46,4090.92 h60
  text "OUTER:" at 11689.46,4086.64 h60
  text "X" at 12084,4086 h60
  text "1.4MIL (1oz)" at 12212.46,3933.92 h60
  text "2.8MIL (2oz)" at 12979.46,3933.92 h60
  text "N/A" at 13706,3934.29 h60
  text "INNER SIGNAL:" at 11400.38,3929.64 h60
  text "X" at 12085.42,3929.64 h60
  text "DRILLING:" at 11332.46,3790.64 h60
  text "REFERENCE:" at 11407.23,3673.64 h60
  text "X" at 12055.46,3673.64 h60
  text "AS SHOWN" at 12242.46,3673.64 h60
  text "X" at 12956.46,3673.64 h60
  text "NC_DRILL FILES" at 13093.46,3673.64 h60
  text "PTH MIN COPPER THICKNESS:" at 11407.23,3515.64 h60
  text "X" at 12757.46,3515.64 h60
  text "1MIL" at 12894.46,3515.64 h60
  text "OTHER" at 13391.46,3515.64 h60
  text "BOARD FINISH:" at 11332.46,3356.64 h60
  text "SILKSCREEN:" at 11487.68,3238.64 h60
  text "X" at 12436.46,3238.64 h60
  text "TOP" at 12562.46,3238.64 h60
  text "X" at 12946.46,3238.64 h60
  text "BOTTOM" at 13073.46,3238.64 h60
  text "SILKSCREEN COLOR:" at 11487.68,3071.64 h60
  text "X" at 12435.42,3071.64 h60
  text "WHITE" at 12562.46,3071.64 h60
  text "OTHER" at 13073.46,3071.64 h60
  text "SOLDER RESIST COLOR:" at 11487.68,2901.64 h60
  text "X" at 12055.42,2742.44 h60
  text "GREEN" at 12182.46,2742.44 h60
  text "BLUE" at 12773.46,2742.44 h60
  text "OTHER" at 13311.46,2742.44 h60
  text "IMMERSION GOLD (ENIG)" at 12393.46,2553.92 h60
  text "ENEPIG" at 13731,2550.64 h60
  text "SURFACE FINISH:" at 11332.46,2549.64 h60
  text "X" at 12206.51,2549.64 h60
  text "IMM. TIN/SILVER OR EQUIV" at 11662,2392.64 h60
  text "OTHER" at 13093.46,2392.64 h60
  text "ARRAY/PANEL:" at 11332.46,2213.64 h60
  text "CUT AND TRIM PER MECH LAYER 1" at 12393.46,2209.35 h60
  text "N.C. ROUTE" at 12393.46,2057.64 h60
  text "X" at 13072.46,2057.64 h60
  text "V. SCORE" at 13259.46,2057.64 h60
  text "CERTIFICATION:" at 11332.46,1920.64 h60
  text "MATERIALS AND WORKMANSHIP FOR ALL PCBS" at 12057.46,1920.64 h60
  text "TO MEET OR EXCEED THE REQUIREMENTS OF:" at 12057.46,1822.64 h60
  text "X" at 11683.96,1686.13 h60
  text "ANSI IPC-A-600F CLASS ->" at 11822.96,1686.13 h60
  text "X" at 13462.02,1686.13 h60
  text "2" at 13580.96,1686.14 h60
  text "1" at 13265.96,1684.64 h60
  text "3" at 13934.96,1684.64 h60
  text "X" at 11686.02,1526.64 h60
  text "UL 94V-0" at 11822.96,1526.64 h60
  text "X" at 12498.02,1526.64 h60
  text "RoHS" at 12634.96,1526.64 h60
  text "OTHER" at 13279.36,1526.64 h60
  text "PER ORDER" at 13676.42,1526.64 h60
  text "ADDITIONAL REQUIREMENTS:" at 11332.46,1385.64 h60
  text "MICROSECTION:" at 11407.23,1270.64 h60
  text "YES" at 12312.96,1270.64 h60
  text "REQUIRED" at 13174.46,1114.49 h60
  text "BARE BOARD ELEC. TEST:" at 11407.23,1111.64 h60
  text "NONE" at 12712.96,1111.64 h60
  text "X" at 13047.46,1111.64 h60
  text "PER ORDER" at 13766.46,1111.64 h60
  text "MANUFACTURER'S UL:" at 11407.23,954.64 h60
  text "RAIL" at 12572.96,950.35 h60
  text "METAL" at 13064.77,950.35 h60
  text "X" at 13440,950 h60
  text "SILK" at 13576.46,950.35 h60
  text ".Layer_Name" at 577,-858.49 h60
M11 Gerber Information:
  lines w10: -292,-930.17 6308,-930.17 ; -292,-726.83 6310,-726.83 ; -292,-523.5 -292,-1133.5 3713,-1133.5 6310,-1133.5 6310,-523.5 -291.5,-523.5 -291.5,-1133.5 1284,-1133.5 ; 2173,-1133.5 2173,-523.5 ; 3440,-726.83 3440,-523.5 ; 4280,-726.83 4280,-523.5 ; 4902,-1140 4902,-937.17
  text "ALL ARTWORK VIEWED FROM TOP SIDE" at -228.5,-655.67 h60
  text "BOARD #:" at 2248,-655.67 h60
  text ".PRJ_Number" at 2793.5,-655.67 h60
  text "REV:" at 3638,-655.67 h60
  text ".PCB_Rev" at 3929.5,-655.67 h60
  text "SVN REV:" at 4476,-655.67 h60
  text ".VersionControl_RevNumber" at 4982,-655.67 h60
  text "LAYER NAME =" at -228.5,-858.49 h60
  text "PLOT NAME =" at -228.5,-1064.34 h60
  text ".plot_File_Name" at 577,-1064.34 h60
  text "GENERATED    :" at 2250,-1064.34 h60
  text ".Print_Date" at 3119.5,-1064.34 h60
  text ".Print_Time" at 3848.5,-1064.34 h60
  text "TEXAS INSTRUMENTS" at 5113,-1064.34 h60
M12 Stackup:
  lines w6: 11360,7460 13910,7460 ; 11360,7564.4 13910,7564.4 ; 11300,6975 ccw(c11334,6975) 11334,6941 13936,6941 ccw(c13936,6975) 13970,6975 13970,7681 ccw(c13936,7681) 13936,7715 11334,7715 ccw(c11334,7681) 11300,7681 11300,6975
  text "The Stackup Legend below this is static." at 11605.5,7874.5 h60
  text "If you change the stackup, update the Legend." at 11615.5,7784.5 h60
  text "Layer Stack Up Detail for: Ref_Design.PcbDoc" at 11360,7597.1 h57
  text "Layer" at 11360,7525.4 h24
  text "Gerber" at 12255.81,7525.4 h24
  text "Copper" at 12819.33,7525.4 h24
  text "Dielectric" at 13422.04,7525.4 h24
  text "Name" at 11360,7477.4 h24
  text "Document" at 12255.81,7477.4 h24
  text "Thickness" at 12819.33,7477.4 h24
  text "Material" at 13422.04,7477.4 h24
  text "Top Solder Mask" at 11360,7384.44 h34
  text "(.GTS)" at 12255.81,7384.44 h34
  text "Solder Resist" at 13422.04,7384.44 h34
  text "Top Layer" at 11360,7287.69 h34
  text "(.GTL)" at 12255.81,7287.69 h34
  text "1.4mil" at 12819.33,7287.69 h34
  text "FR-4" at 13422.04,7239.31 h34
  text "Bottom Layer" at 11360,7190.94 h34
  text "(.GBL)" at 12255.81,7190.94 h34
  text "1.4mil" at 12819.33,7190.94 h34
  text "Bottom Solder Mask" at 11360,7094.19 h34
  text "(.GBS)" at 12255.81,7094.19 h34
  text "Solder Resist" at 13422.04,7094.19 h34
  text ".Layer_Name" at 577,-858.49 h60
M13 Component Bodies Top:
  text ".Layer_Name" at 577,-858.49 h60
M14 Component Bodies Bottom:
  text ".Layer_Name" at 577,-858.49 h60
M15 Courtyards Top:
  text ".Layer_Name" at 577,-858.49 h60
M16 Courtyards Bottom:
  text ".Layer_Name" at 577,-858.49 h60
Drill Drawing:
  text ".legend" at 5122.5,725.5 h60
  text "Drill Table" at 5147.5,540.5 h60
  text ".Layer_Name" at 577,-858.49 h60

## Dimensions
0,0 to 2000,0 on M2 Board Dimensions
0,0 to 0,2700 on M2 Board Dimensions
